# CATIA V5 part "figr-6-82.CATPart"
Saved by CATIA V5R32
Part number: Part1
Bounding box of the stored display mesh (mm): x -34 to 138.458, y -76 to 68, z 0 to 192.551
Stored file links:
  D:\PROJECTS\Project 2022\CATIA V5 6R 2022\Resources\Part Files\c06_catia_v5_6r2022_prt\figr-6-82.CATPart
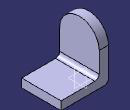
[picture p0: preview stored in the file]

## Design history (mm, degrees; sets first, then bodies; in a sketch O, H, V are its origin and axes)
Body1 (main body)
  Sketch1 on zx-plane, origin (0, 0, 0), H (-1, 0, 0), V (0, 0, 1)
    line L1 (-138.4578, 31.0171) -> (0, 31.0171)
    line L2 (0, 31.0171) -> (0, 0)
    line L3 (0, 0) -> (-138.4578, 0)
    line L4 (-138.4578, 0) -> (-138.4578, 31.0171)
    horizontal: L1 H, L3 H
    vertical: L2 V, L4 V
  Pad1: profile Sketch1, direction (0, 1, 0), length 68, opposite side length 76
  Sketch2 on face of Pad1 from Sketch1.L2, origin (0, 0, 0), H (0, -1, 0), V (0, 0, 1)
    point P1 (-68, 0)
    line L1 (-68, 0) -> (-68, 120.5512)
    arc A1 centre (4, 120.5512) radius 72 from (-68, 120.5512) to (76, 120.5512) cw
    line L2 (76, 120.5512) -> (76, 0)
    point P5 (76, 0)
    line L3 (76, 0) -> (-68, 0)
    reference projected line E1 (-68, 0) -> (-68, 31.0171) from edge [face of Pad1 from Sketch1.L2 | end face of Pad1]
    reference projected line E2 (76, 0) -> (76, 31.0171) from edge [start face of Pad1 | face of Pad1 from Sketch1.L2]
    reference projected line E3 (76, 0) -> (76, 31.0171) from edge [start face of Pad1 | face of Pad1 from Sketch1.L2]
    coincidence: P1 H, P5 H
    vertical: L1 V
    tangency: A1 L1, L2 A1, L1 E1, L2 E3
    horizontal: L3 H
    parallelism: L2 E2
  Pad2: profile Sketch2, direction (-1, 0, 0), length 34
  Fillet1: radius 15, on edge [face of Pad1 from Sketch1.L1 | start face of Pad2]
  Shell1: ExtOffset 0, Face (end face of Pad2; face of Pad2), IntOffset 5
  Fillet2: radius 15, on edge [face of Pad2 | end face of Pad2] (x2)
  RemoveFace1: KeepFaces (face of Pad2; face of Fillet2; end face of Pad2; face of Fillet2), RemoveFaces (face of Shell1; face of Shell1; face of Shell1)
